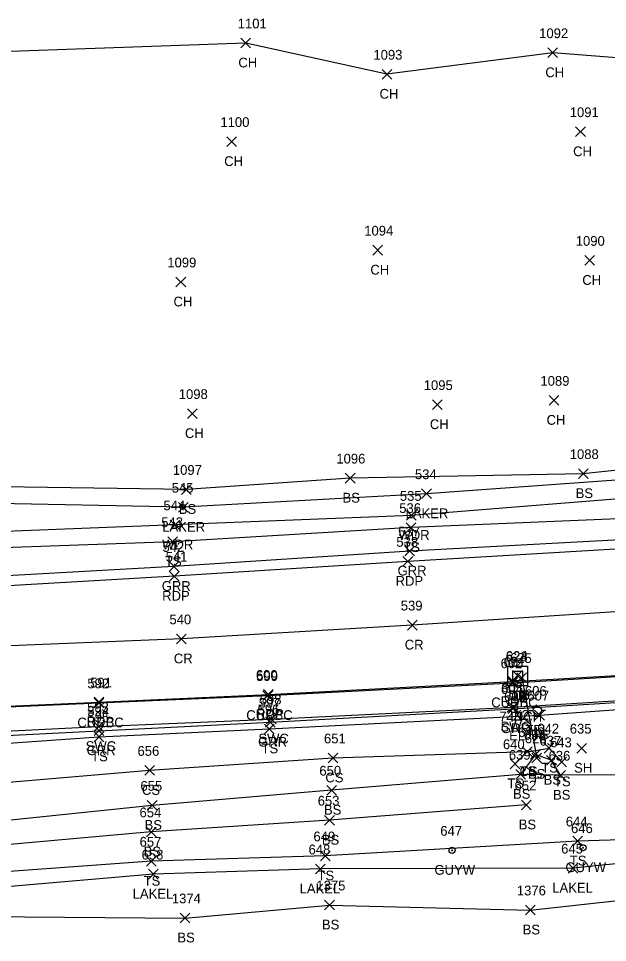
# Model space of a CAD drawing. Extents: x 1715662 to 1717487, y 887396 to 890004.
# Drawn here: x 1717238 to 1717358.8, y 888190.5 to 888379.8 of the extents above; entities that cross this region are included whole.
import ezdxf

# ---------------------------------------------------------------- set-up
doc = ezdxf.new("R2010")
doc.units = 0
for name, color, linetype in [('D_A', 7, 'Continuous'), ('D_C', 7, 'Continuous'), ('D_I', 7, 'Continuous'), ('D_TIC', 7, 'Continuous'), ('DCP', 7, 'Continuous'), ('DS', 7, 'Continuous'), ('L_A', 7, 'Continuous'), ('L_I', 7, 'Continuous'), ('L_TIC', 7, 'Continuous'), ('LAWA', 7, 'Continuous'), ('LAWE', 7, 'Continuous'), ('LELB', 7, 'Continuous'), ('LSOGP', 7, 'Continuous'), ('P_A', 7, 'Continuous'), ('P_I', 7, 'Continuous'), ('P_TIC', 7, 'Continuous'), ('PET', 7, 'Continuous'), ('PRC', 7, 'Continuous'), ('R_A', 7, 'Continuous'), ('R_I', 7, 'Continuous'), ('R_TIC', 7, 'Continuous'), ('RC', 7, 'Continuous'), ('RGR', 7, 'Continuous'), ('RSW', 7, 'Continuous'), ('U_A', 7, 'Continuous'), ('U_I', 7, 'Continuous'), ('UEPT', 7, 'Continuous'), ('UP', 7, 'Continuous'), ('UPGW', 7, 'Continuous')]:
    doc.layers.add(name, color=color, linetype=linetype)

msp = doc.modelspace()

# ---------------------------------------------------------------- linework, layer by layer
at = {"layer": 'D_TIC'}
for points in [[(1717339.35, 888244.19), (1717341.35, 888246.19)], [(1717341.35, 888244.19), (1717339.35, 888246.19)], [(1717340.21, 888243.77), (1717342.21, 888245.77)], [(1717342.21, 888243.77), (1717340.21, 888245.77)], [(1717343.3, 888227.29), (1717345.3, 888229.29)], [(1717345.3, 888227.29), (1717343.3, 888229.29)]]:
    msp.add_lwpolyline(points, dxfattribs=at)
at = {"layer": 'DCP'}
msp.add_lwpolyline([(1717341.21, 888244.77), (1717344.3, 888228.29)], dxfattribs=at)
at = {"layer": 'DS'}
for p, q in [((1717338.38, 888247.11), (1717342.38, 888247.11)), ((1717338.38, 888243.11), (1717338.38, 888247.11)), ((1717339.38, 888244.11), (1717339.38, 888246.11)), ((1717339.38, 888246.11), (1717341.38, 888246.11)), ((1717341.38, 888246.11), (1717341.38, 888244.11)), ((1717342.38, 888247.11), (1717342.38, 888243.11)), ((1717340.38, 888245.11), (1717340.38, 888245.11)), ((1717340.38, 888245.11), (1717340.38, 888245.11)), ((1717342.38, 888243.11), (1717338.38, 888243.11)), ((1717341.38, 888244.11), (1717339.38, 888244.11))]:
    msp.add_line(p, q, dxfattribs=at)
at = {"layer": 'L_TIC'}
for points in [[(1717283.62, 888373.82), (1717285.62, 888375.82)], [(1717285.62, 888373.82), (1717283.62, 888375.82)], [(1717346.56, 888371.82), (1717348.56, 888373.82)], [(1717348.56, 888371.82), (1717346.56, 888373.82)], [(1717312.58, 888367.41), (1717314.58, 888369.41)], [(1717314.58, 888367.41), (1717312.58, 888369.41)], [(1717352.26, 888355.63), (1717354.26, 888357.63)], [(1717354.26, 888355.63), (1717352.26, 888357.63)], [(1717280.72, 888353.61), (1717282.72, 888355.61)], [(1717282.72, 888353.61), (1717280.72, 888355.61)], [(1717310.69, 888331.36), (1717312.69, 888333.36)], [(1717312.69, 888331.36), (1717310.69, 888333.36)], [(1717354.15, 888329.26), (1717356.15, 888331.26)], [(1717356.15, 888329.26), (1717354.15, 888331.26)], [(1717270.32, 888324.84), (1717272.32, 888326.84)], [(1717272.32, 888324.84), (1717270.32, 888326.84)], [(1717322.89, 888299.7), (1717324.89, 888301.7)], [(1717324.89, 888299.7), (1717322.89, 888301.7)], [(1717346.82, 888300.58), (1717348.82, 888302.58)], [(1717348.82, 888300.58), (1717346.82, 888302.58)], [(1717272.66, 888297.86), (1717274.66, 888299.86)], [(1717274.66, 888297.86), (1717272.66, 888299.86)], [(1717305.03, 888284.64), (1717307.03, 888286.64)], [(1717307.03, 888284.64), (1717305.03, 888286.64)], [(1717352.83, 888285.56), (1717354.83, 888287.56)], [(1717354.83, 888285.56), (1717352.83, 888287.56)], [(1717271.45, 888282.32), (1717273.45, 888284.32)], [(1717273.45, 888282.32), (1717271.45, 888284.32)], [(1717320.69, 888281.44), (1717322.69, 888283.44)], [(1717322.69, 888281.44), (1717320.69, 888283.44)], [(1717270.81, 888278.67), (1717272.81, 888280.67)], [(1717272.81, 888278.67), (1717270.81, 888280.67)], [(1717317.58, 888277), (1717319.58, 888279)], [(1717319.58, 888277), (1717317.58, 888279)], [(1717269.11, 888275.06), (1717271.11, 888277.06)], [(1717271.11, 888275.06), (1717269.11, 888277.06)], [(1717317.52, 888274.5), (1717319.52, 888276.5)], [(1717319.52, 888274.5), (1717317.52, 888276.5)], [(1717268.66, 888271.61), (1717270.66, 888273.61)], [(1717270.66, 888271.61), (1717268.66, 888273.61)], [(1717343.86, 888236.07), (1717345.86, 888238.07)], [(1717345.86, 888236.07), (1717343.86, 888238.07)], [(1717288.45, 888233.25), (1717290.45, 888235.25)], [(1717290.45, 888233.25), (1717288.45, 888235.25)], [(1717253.51, 888231.62), (1717255.51, 888233.62)], [(1717255.51, 888231.62), (1717253.51, 888233.62)], [(1717345.81, 888229.31), (1717347.81, 888231.31)], [(1717347.81, 888229.31), (1717345.81, 888231.31)], [(1717352.48, 888229.29), (1717354.48, 888231.29)], [(1717354.48, 888229.29), (1717352.48, 888231.29)], [(1717301.51, 888227.29), (1717303.51, 888229.29)], [(1717303.51, 888227.29), (1717301.51, 888229.29)], [(1717341.32, 888228.58), (1717343.32, 888230.58)], [(1717343.32, 888228.58), (1717341.32, 888230.58)], [(1717341.32, 888228.58), (1717343.32, 888230.58)], [(1717343.32, 888228.58), (1717341.32, 888230.58)], [(1717343.04, 888228.04), (1717345.04, 888230.04)], [(1717345.04, 888228.04), (1717343.04, 888230.04)], [(1717338.85, 888226.1), (1717340.85, 888228.1)], [(1717340.85, 888226.1), (1717338.85, 888228.1)], [(1717346.26, 888226.83), (1717348.26, 888228.83)], [(1717348.26, 888226.83), (1717346.26, 888228.83)], [(1717348.42, 888226.49), (1717350.42, 888228.49)], [(1717350.42, 888226.49), (1717348.42, 888228.49)], [(1717263.9, 888224.74), (1717265.9, 888226.74)], [(1717265.9, 888224.74), (1717263.9, 888226.74)], [(1717339.99, 888223.94), (1717341.99, 888225.94)], [(1717341.99, 888223.94), (1717339.99, 888225.94)], [(1717339.99, 888223.94), (1717341.99, 888225.94)], [(1717341.99, 888223.94), (1717339.99, 888225.94)], [(1717348.19, 888223.75), (1717350.19, 888225.75)], [(1717350.19, 888223.75), (1717348.19, 888225.75)], [(1717348.19, 888223.75), (1717350.19, 888225.75)], [(1717350.19, 888223.75), (1717348.19, 888225.75)], [(1717301.22, 888220.68), (1717303.22, 888222.68)], [(1717303.22, 888220.68), (1717301.22, 888222.68)], [(1717264.44, 888217.58), (1717266.44, 888219.58)], [(1717266.44, 888217.58), (1717264.44, 888219.58)], [(1717341.15, 888217.66), (1717343.15, 888219.66)], [(1717343.15, 888217.66), (1717341.15, 888219.66)], [(1717300.79, 888214.53), (1717302.79, 888216.53)], [(1717302.79, 888214.53), (1717300.79, 888216.53)], [(1717264.25, 888212.13), (1717266.25, 888214.13)], [(1717266.25, 888212.13), (1717264.25, 888214.13)], [(1717351.66, 888210.27), (1717353.66, 888212.27)], [(1717353.66, 888210.27), (1717351.66, 888212.27)], [(1717299.92, 888207.21), (1717301.92, 888209.21)], [(1717301.92, 888207.21), (1717299.92, 888209.21)], [(1717264.27, 888206.12), (1717266.27, 888208.12)], [(1717266.27, 888206.12), (1717264.27, 888208.12)], [(1717298.91, 888204.55), (1717300.91, 888206.55)], [(1717300.91, 888204.55), (1717298.91, 888206.55)], [(1717350.71, 888204.71), (1717352.71, 888206.71)], [(1717352.71, 888204.71), (1717350.71, 888206.71)], [(1717264.68, 888203.48), (1717266.68, 888205.48)], [(1717266.68, 888203.48), (1717264.68, 888205.48)], [(1717300.8, 888197.15), (1717302.8, 888199.15)], [(1717302.8, 888197.15), (1717300.8, 888199.15)], [(1717341.96, 888196.13), (1717343.96, 888198.13)], [(1717343.96, 888196.13), (1717341.96, 888198.13)], [(1717271.16, 888194.5), (1717273.16, 888196.5)], [(1717273.16, 888194.5), (1717271.16, 888196.5)]]:
    msp.add_lwpolyline(points, dxfattribs=at)
at = {"layer": 'LAWA'}
msp.add_lwpolyline([(1717427.07, 888329.96), (1717424.15, 888313.24), (1717417.81, 888299.74), (1717405.98, 888286.01), (1717373.07, 888282.35), (1717318.58, 888278), (1717270.11, 888276.06), (1717231.85, 888274.55), (1717204.52, 888271.65)], dxfattribs=at)
at = {"layer": 'LAWE'}
for points in [[(1717421.68, 888328.92), (1717420.89, 888312.99), (1717415.11, 888301.4), (1717401.41, 888289.2), (1717371, 888285.95), (1717321.69, 888282.44), (1717271.81, 888279.67), (1717230.21, 888280.53), (1717194.5, 888279.04), (1717177.12, 888274.47), (1717174.06, 888271.23), (1717172.86, 888266.22)], [(1717428.73, 888210.05), (1717391.62, 888209.76), (1717351.71, 888205.71), (1717299.91, 888205.55), (1717265.68, 888204.48), (1717223.67, 888200.84), (1717208.56, 888201.76), (1717201.77, 888208.17), (1717191.38, 888215.04), (1717175.77, 888226.39)]]:
    msp.add_lwpolyline(points, dxfattribs=at)
at = {"layer": 'LELB'}
for points in [[(1717397.44, 888368.91), (1717401.94, 888364.63), (1717406.07, 888347.48), (1717411.38, 888343.28), (1717409.79, 888309.96), (1717403.02, 888297.91), (1717392.21, 888290.65), (1717353.83, 888286.56), (1717306.03, 888285.64), (1717272.45, 888283.32), (1717220.2, 888284.1), (1717193.83, 888280.31), (1717176.82, 888276.72), (1717169.82, 888270.77)], [(1717414.27, 888287.03), (1717406.99, 888281.7), (1717373.99, 888277.88), (1717318.52, 888275.5), (1717269.66, 888272.61), (1717230.91, 888271.26), (1717203.91, 888268.9), (1717185.06, 888265.29), (1717179.22, 888264.43), (1717179.32, 888261.72)], [(1717168.22, 888251.6), (1717169.76, 888223.63), (1717177.45, 888214.69), (1717194.47, 888204.09), (1717205.17, 888197.96), (1717222.8, 888195.9), (1717272.16, 888195.5), (1717301.8, 888198.15), (1717342.96, 888197.13), (1717391.28, 888202.44), (1717438.03, 888204.25)], [(1717195, 888228.65), (1717213.42, 888229.75), (1717254.51, 888232.62), (1717289.45, 888234.25), (1717344.86, 888237.07), (1717388.41, 888240.22), (1717429.71, 888242.89)], [(1717342.32, 888229.58), (1717302.51, 888228.29), (1717264.9, 888225.74), (1717212.77, 888221.26), (1717194.86, 888221.27), (1717182.07, 888225.99)], [(1717339.85, 888227.1), (1717342.32, 888229.58), (1717346.81, 888230.31), (1717349.42, 888227.49)], [(1717349.19, 888224.75), (1717347.26, 888227.83), (1717344.04, 888229.04), (1717340.99, 888224.94)], [(1717429.58, 888226.27), (1717393.83, 888225.01), (1717349.19, 888224.75), (1717340.99, 888224.94), (1717302.22, 888221.68), (1717265.44, 888218.58), (1717217.95, 888213.61)], [(1717342.15, 888218.66), (1717301.79, 888215.53), (1717265.25, 888213.13), (1717219.42, 888209.07), (1717204.97, 888210.23)], [(1717429.06, 888212.61), (1717392.81, 888212.48), (1717352.66, 888211.27), (1717300.92, 888208.21), (1717265.27, 888207.12), (1717222.12, 888203.99)]]:
    msp.add_lwpolyline(points, dxfattribs=at)
at = {"layer": 'LSOGP'}
msp.add_lwpolyline([(1717397.44, 888368.91), (1717347.56, 888372.82), (1717313.58, 888368.41), (1717284.61, 888374.82), (1717226.58, 888372.74), (1717200.46, 888359.46), (1717144.02, 888346.31), (1717139.03, 888337.96), (1717115.57, 888330.22), (1717057.48, 888334.02)], dxfattribs=at)
at = {"layer": 'P_TIC'}
for points in [[(1717316.86, 888267.58), (1717318.86, 888269.58)], [(1717318.86, 888267.58), (1717316.86, 888269.58)], [(1717269, 888264.54), (1717271, 888266.54)], [(1717271, 888264.54), (1717269, 888266.54)], [(1717317.78, 888254.52), (1717319.78, 888256.52)], [(1717319.78, 888254.52), (1717317.78, 888256.52)], [(1717270.43, 888251.69), (1717272.43, 888253.69)], [(1717272.43, 888251.69), (1717270.43, 888253.69)], [(1717338.42, 888242.96), (1717340.42, 888244.96)], [(1717340.42, 888242.96), (1717338.42, 888244.96)], [(1717288.28, 888240.31), (1717290.28, 888242.31)], [(1717290.28, 888240.31), (1717288.28, 888242.31)], [(1717253.52, 888238.74), (1717255.52, 888240.74)], [(1717255.52, 888238.74), (1717253.52, 888240.74)]]:
    msp.add_lwpolyline(points, dxfattribs=at)
at = {"layer": 'PET'}
msp.add_lwpolyline([(1717427.27, 888275.57), (1717374.24, 888271.92), (1717317.86, 888268.58), (1717270, 888265.54), (1717231.18, 888263.33), (1717177.06, 888260.69), (1717177.8, 888248.05), (1717178.6, 888236.51), (1717214.03, 888237.98), (1717254.52, 888239.74), (1717289.28, 888241.31), (1717339.42, 888243.96), (1717387.67, 888246.79), (1717419.3, 888248.63), (1717429.05, 888249.53)], dxfattribs=at)
at = {"layer": 'PRC'}
msp.add_lwpolyline([(1717428.93, 888262.88), (1717374.93, 888259.17), (1717318.78, 888255.52), (1717271.43, 888252.69), (1717231.27, 888251.09), (1717177.8, 888248.05)], dxfattribs=at)
at = {"layer": 'R_TIC'}
for points in [[(1717317.26, 888269.69), (1717319.26, 888271.69)], [(1717319.26, 888269.69), (1717317.26, 888271.69)], [(1717268.91, 888266.54), (1717270.91, 888268.54)], [(1717270.91, 888266.54), (1717268.91, 888268.54)], [(1717338.38, 888242.69), (1717340.38, 888244.69)], [(1717340.38, 888242.69), (1717338.38, 888244.69)], [(1717253.52, 888238.57), (1717255.52, 888240.57)], [(1717255.52, 888238.57), (1717253.52, 888240.57)], [(1717288.15, 888240.08), (1717290.15, 888242.08)], [(1717290.15, 888240.08), (1717288.15, 888242.08)], [(1717338.45, 888237.4), (1717340.45, 888239.4)], [(1717340.45, 888237.4), (1717338.45, 888239.4)], [(1717338.5, 888237.74), (1717340.5, 888239.74)], [(1717340.5, 888237.74), (1717338.5, 888239.74)], [(1717288.66, 888234.62), (1717290.66, 888236.62)], [(1717290.66, 888234.62), (1717288.66, 888236.62)], [(1717288.86, 888235.28), (1717290.86, 888237.28)], [(1717290.86, 888235.28), (1717288.86, 888237.28)], [(1717253.44, 888233.73), (1717255.44, 888235.73)], [(1717255.44, 888233.73), (1717253.44, 888235.73)], [(1717253.51, 888232.87), (1717255.51, 888234.87)], [(1717255.51, 888232.87), (1717253.51, 888234.87)]]:
    msp.add_lwpolyline(points, dxfattribs=at)
at = {"layer": 'RC'}
msp.add_lwpolyline([(1717178.77, 888236.27), (1717214.14, 888237.8), (1717254.52, 888239.57), (1717289.15, 888241.08), (1717339.38, 888243.69), (1717387.75, 888246.62), (1717419.31, 888248.49), (1717429.07, 888249.37)], dxfattribs=at)
at = {"layer": 'RGR'}
for points in [[(1717414.46, 888276.43), (1717374.09, 888273.7), (1717318.26, 888270.69), (1717269.91, 888267.54), (1717230.71, 888265.34), (1717183.33, 888262.06)], [(1717180.01, 888230.78), (1717185.31, 888230.2), (1717193.48, 888230.86), (1717213.85, 888231.84), (1717254.51, 888233.87), (1717289.66, 888235.62), (1717339.45, 888238.4), (1717388.12, 888241.37), (1717429.56, 888243.99)]]:
    msp.add_lwpolyline(points, dxfattribs=at)
at = {"layer": 'RSW'}
msp.add_lwpolyline([(1717178.7, 888235.76), (1717178.9, 888231.46), (1717213.38, 888232.72), (1717254.44, 888234.73), (1717289.86, 888236.28), (1717339.5, 888238.74), (1717388.22, 888241.81), (1717419.75, 888243.67), (1717429.73, 888244.54)], dxfattribs=at)
at = {"layer": 'UEPT'}
for p, q in [((1717340.26, 888238.55), (1717340.09, 888237.71)), ((1717339.26, 888236.05), (1717339.26, 888237.71)), ((1717339.26, 888237.71), (1717340.92, 888237.71)), ((1717340.09, 888236.88), (1717340.09, 888236.88)), ((1717340.92, 888237.71), (1717340.92, 888236.05)), ((1717340.92, 888236.05), (1717339.26, 888236.05)), ((1717339.84, 888235.21), (1717340.09, 888236.05))]:
    msp.add_line(p, q, dxfattribs=at)
at = {"layer": 'UP'}
for p, q in [((1717342.75, 888238.04), (1717343.58, 888238.04)), ((1717344.41, 888238.05), (1717344.41, 888238.05)), ((1717346.08, 888238.05), (1717345.24, 888238.05)), ((1717345.24, 888238.05), (1717345.24, 888238.05)), ((1717346.08, 888238.05), (1717346.08, 888238.05))]:
    msp.add_line(p, q, dxfattribs=at)
msp.add_circle((1717344.41, 888238.05), 0.833, dxfattribs=at)
at = {"layer": 'UPGW'}
for centre, radius in [((1717353.78, 888209.9), 0.625), ((1717326.93, 888209.36), 0.625), ((1717326.93, 888209.36), 0.0833), ((1717353.78, 888209.9), 0.0833)]:
    msp.add_circle(centre, radius, dxfattribs=at)

# ---------------------------------------------------------------- texts
at = {"layer": 'D_A'}
for s, p in [('DIB', (1717338.45, 888240.19)), ('DI', (1717339.44, 888240.11)), ('P', (1717340.59, 888239.77)), ('P', (1717343.68, 888223.29))]:
    msp.add_text(s, height=2, dxfattribs=at).set_placement(p)
at = {"layer": 'D_C'}
for s, p in [('7 INCH', (1717336.63, 888235.77)), ('2X2', (1717337.96, 888236.11))]:
    msp.add_text(s, height=2, dxfattribs=at).set_placement(p)
at = {"layer": 'D_I'}
for s, p in [('624', (1717337.94, 888248.19)), ('623', (1717337.97, 888248.11)), ('625', (1717338.81, 888247.77)), ('626', (1717341.84, 888231.29))]:
    msp.add_text(s, height=2, dxfattribs=at).set_placement(p)
at = {"layer": 'L_A'}
for s, p in [('CH', (1717283.11, 888369.82)), ('CH', (1717346.05, 888367.82)), ('CH', (1717312.06, 888363.41)), ('CH', (1717351.75, 888351.63)), ('CH', (1717280.21, 888349.61)), ('CH', (1717310.18, 888327.36)), ('CH', (1717353.64, 888325.26)), ('CH', (1717269.81, 888320.84)), ('CH', (1717322.38, 888295.7)), ('CH', (1717346.31, 888296.58)), ('CH', (1717272.15, 888293.86)), ('BS', (1717304.47, 888280.64)), ('BS', (1717352.27, 888281.56)), ('BS', (1717270.89, 888278.32)), ('LAKER', (1717317.39, 888277.44)), ('LAKER', (1717267.52, 888274.67)), ('WDR', (1717315.94, 888273)), ('WDR', (1717267.47, 888271.06)), ('TS', (1717316.93, 888270.5)), ('TS', (1717268.07, 888267.61)), ('TS', (1717343.27, 888232.07)), ('TS', (1717287.86, 888229.25)), ('TS', (1717252.92, 888227.62)), ('TS', (1717345.22, 888225.31)), ('SH', (1717351.96, 888225.29)), ('CS', (1717300.95, 888223.29)), ('TS', (1717340.73, 888224.58)), ('CS', (1717340.76, 888224.58)), ('BS', (1717342.48, 888224.04)), ('TS', (1717338.26, 888222.1)), ('BS', (1717345.71, 888222.83)), ('TS', (1717347.83, 888222.49)), ('CS', (1717263.34, 888220.74)), ('BS', (1717339.43, 888219.94)), ('BS', (1717339.43, 888219.94)), ('BS', (1717347.63, 888219.75)), ('BS', (1717347.63, 888219.75)), ('BS', (1717300.66, 888216.68)), ('BS', (1717263.88, 888213.58)), ('BS', (1717340.59, 888213.66)), ('BS', (1717300.23, 888210.53)), ('BS', (1717263.69, 888208.13)), ('TS', (1717351.07, 888206.27)), ('TS', (1717299.33, 888203.21)), ('TS', (1717263.68, 888202.12)), ('LAKEL', (1717295.67, 888200.55)), ('LAKEL', (1717347.48, 888200.71)), ('LAKEL', (1717261.44, 888199.48)), ('BS', (1717300.24, 888193.15)), ('BS', (1717341.4, 888192.13)), ('BS', (1717270.6, 888190.5))]:
    msp.add_text(s, height=2, dxfattribs=at).set_placement(p)
at = {"layer": 'L_I'}
for s, p in [('1101', (1717282.98, 888377.82)), ('1092', (1717344.79, 888375.82)), ('1093', (1717310.8, 888371.41)), ('1091', (1717351.06, 888359.63)), ('1100', (1717279.43, 888357.61)), ('1094', (1717308.92, 888335.36)), ('1090', (1717352.29, 888333.26)), ('1099', (1717268.54, 888328.84)), ('1095', (1717321.12, 888303.7)), ('1089', (1717345.05, 888304.58)), ('1098', (1717270.89, 888301.86)), ('1088', (1717351.06, 888289.56)), ('1096', (1717303.2, 888288.64)), ('1097', (1717269.68, 888286.32)), ('534', (1717319.32, 888285.44)), ('545', (1717269.45, 888282.67)), ('535', (1717316.22, 888281)), ('544', (1717267.75, 888279.06)), ('536', (1717316.1, 888278.5)), ('543', (1717267.3, 888275.61)), ('607', (1717342.37, 888240.07)), ('596', (1717287.04, 888237.25)), ('595', (1717252.15, 888235.62)), ('642', (1717344.4, 888233.31)), ('635', (1717351.07, 888233.29)), ('651', (1717300.67, 888231.29)), ('641', (1717340.48, 888232.58)), ('641', (1717340.48, 888232.58)), ('638', (1717341.63, 888232.04)), ('637', (1717344.85, 888230.83)), ('640', (1717337.36, 888230.1)), ('643', (1717347.01, 888230.49)), ('656', (1717262.43, 888228.74)), ('639', (1717338.57, 888227.94)), ('639', (1717338.57, 888227.94)), ('636', (1717346.72, 888227.75)), ('636', (1717346.72, 888227.75)), ('650', (1717299.72, 888224.68)), ('655', (1717263.03, 888221.58)), ('652', (1717339.74, 888221.66)), ('653', (1717299.38, 888218.53)), ('654', (1717262.84, 888216.13)), ('644', (1717350.25, 888214.27)), ('657', (1717262.86, 888210.12)), ('649', (1717298.5, 888211.21)), ('648', (1717297.5, 888208.55)), ('645', (1717349.3, 888208.71)), ('658', (1717263.27, 888207.48)), ('1375', (1717299.11, 888201.15)), ('1376', (1717340.22, 888200.13)), ('1374', (1717269.47, 888198.5))]:
    msp.add_text(s, height=2, dxfattribs=at).set_placement(p)
at = {"layer": 'P_A'}
for s, p in [('RDP', (1717315.35, 888263.58)), ('RDP', (1717267.48, 888260.54)), ('CR', (1717317.22, 888250.52)), ('CR', (1717269.87, 888247.69)), ('RDP', (1717336.91, 888238.96)), ('RDP', (1717252.01, 888234.74)), ('RDP', (1717286.77, 888236.31))]:
    msp.add_text(s, height=2, dxfattribs=at).set_placement(p)
at = {"layer": 'P_I'}
for s, p in [('538', (1717315.5, 888271.58)), ('541', (1717268.2, 888268.54)), ('539', (1717316.41, 888258.52)), ('540', (1717268.98, 888255.69)), ('601', (1717337.5, 888246.96)), ('600', (1717286.71, 888244.31)), ('591', (1717252.73, 888242.74))]:
    msp.add_text(s, height=2, dxfattribs=at).set_placement(p)
at = {"layer": 'R_A'}
for s, p in [('GRR', (1717315.75, 888265.69)), ('GRR', (1717267.4, 888262.54)), ('CURBC', (1717334.96, 888238.69)), ('CURBC', (1717250.1, 888234.57)), ('CURBC', (1717284.73, 888236.08)), ('SWC', (1717336.86, 888233.74)), ('GRR', (1717336.94, 888233.4)), ('SWC', (1717287.22, 888231.28)), ('SWC', (1717251.8, 888229.73)), ('GRR', (1717287.15, 888230.62)), ('GRR', (1717252, 888228.87))]:
    msp.add_text(s, height=2, dxfattribs=at).set_placement(p)
at = {"layer": 'R_I'}
for s, p in [('537', (1717315.89, 888273.69)), ('542', (1717267.54, 888270.54)), ('602', (1717336.89, 888246.69)), ('599', (1717286.78, 888244.08)), ('592', (1717252.15, 888242.57)), ('604', (1717336.96, 888241.4)), ('603', (1717337.01, 888241.74)), ('597', (1717287.3, 888238.62)), ('598', (1717287.49, 888239.28)), ('593', (1717252.08, 888237.73)), ('594', (1717252.15, 888236.87))]:
    msp.add_text(s, height=2, dxfattribs=at).set_placement(p)
at = {"layer": 'U_A'}
for s, p in [('TEL', (1717341.97, 888233.05)), ('EL', (1717338.63, 888231.88)), ('GUYW', (1717323.32, 888204.36)), ('GUYW', (1717350.18, 888204.9))]:
    msp.add_text(s, height=2, dxfattribs=at).set_placement(p)
at = {"layer": 'U_I'}
for s, p in [('606', (1717341.87, 888241.05)), ('605', (1717337.6, 888239.88)), ('647', (1717324.52, 888212.36)), ('646', (1717351.32, 888212.9))]:
    msp.add_text(s, height=2, dxfattribs=at).set_placement(p)

doc.saveas('drawing.dxf')
